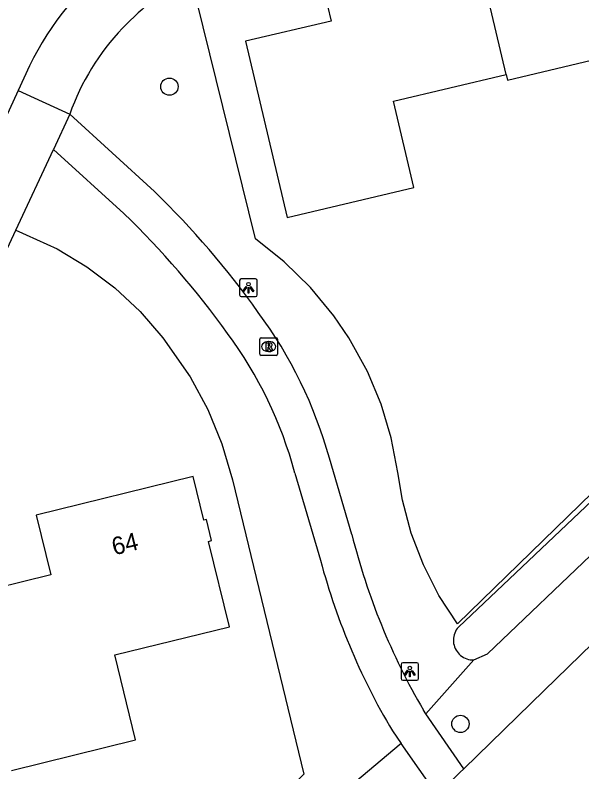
# Model space of a CAD drawing. Extents: x 157663 to 158496, y 379212 to 380934.
# Drawn here: x 158247.41 to 158279.59, y 380475.38 to 380518.31 of the extents above; entities that cross this region are included whole.
import ezdxf

# ---------------------------------------------------------------- set-up
doc = ezdxf.new("R2010")
doc.units = 0
for name, color, linetype in [('IMGEO_Berm_groen', 7, 'Continuous'), ('IMGEO_Boom', 7, 'Continuous'), ('IMGEO_Groenvoorziening', 7, 'Continuous'), ('IMGEO_Lichtpunt', 7, 'Continuous'), ('IMGEO_Pand', 7, 'Continuous'), ('IMGEO_Pand_nummerreeks', 7, 'Continuous'), ('IMGEO_Rijbaan_lokaal_gesloten', 7, 'Continuous'), ('IMGEO_Rijbaan_lokaal_open', 7, 'Continuous'), ('IMGEO_Rioolput', 7, 'Continuous'), ('IMGEO_Voetpad_open', 7, 'Continuous'), ('IMGEO_Waterloop', 7, 'Continuous')]:
    doc.layers.add(name, color=color, linetype=linetype)

msp = doc.modelspace()

# ---------------------------------------------------------------- linework, layer by layer
at = {"layer": 'IMGEO_Berm_groen'}
msp.add_lwpolyline([(158269.334, 380476.98), (158265.254, 380473.57)], dxfattribs=at)
at = {"layer": 'IMGEO_Boom'}
for centre in [(158256.174, 380514.25), (158272.696, 380478.099)]:
    msp.add_circle(centre, 0.489, dxfattribs=at)
at = {"layer": 'IMGEO_Groenvoorziening'}
for points in [[(158329.422, 380539.101), (158289.215, 380500), (158272.525, 380483.772), (158271.474, 380485.392), (158270.597, 380487.114), (158269.906, 380488.917), (158269.406, 380490.783), (158269.143, 380492.356), (158268.772, 380494.324), (158268.197, 380496.241), (158267.425, 380498.089), (158266.367, 380500), (158265.516, 380501.245), (158264.187, 380502.857), (158262.697, 380504.321), (158261.062, 380505.621), (158257.353, 380520.65)], [(158247.453, 380506.107), (158249.805, 380505.05), (158251.493, 380504.031), (158253.066, 380502.84), (158254.505, 380501.492), (158255.796, 380500), (158257.354, 380497.789), (158258.356, 380495.931), (158259.158, 380493.979), (158259.752, 380491.953), (158263.809, 380475.249), (158204.989, 380417.99)], [(158270.73, 380478.676), (158273.465, 380481.728)]]:
    msp.add_lwpolyline(points, dxfattribs=at)
at = {"layer": 'IMGEO_Lichtpunt'}
for p, q in [((158260.161, 380503.246), (158260.161, 380502.439)), ((158260.161, 380503.246), (158260.161, 380502.439)), ((158261.063, 380503.341), (158260.255, 380503.341)), ((158261.063, 380503.341), (158260.255, 380503.341)), ((158261.157, 380502.439), (158261.157, 380503.246)), ((158261.157, 380502.439), (158261.157, 380503.246)), ((158260.255, 380502.345), (158261.063, 380502.345)), ((158260.255, 380502.345), (158261.063, 380502.345)), ((158269.324, 380481.474), (158269.324, 380480.667)), ((158269.324, 380481.474), (158269.324, 380480.667)), ((158270.226, 380481.569), (158269.418, 380481.569)), ((158270.226, 380481.569), (158269.418, 380481.569)), ((158270.32, 380480.667), (158270.32, 380481.474)), ((158270.32, 380480.667), (158270.32, 380481.474)), ((158269.418, 380480.573), (158270.226, 380480.573)), ((158269.418, 380480.573), (158270.226, 380480.573))]:
    msp.add_line(p, q, dxfattribs=at)
for points in [[(158260.535, 380502.91), (158260.574, 380502.882), (158260.386, 380502.62), (158260.348, 380502.647), (158260.535, 380502.91)], [(158260.637, 380502.862), (158260.684, 380502.862), (158260.684, 380502.54), (158260.637, 380502.54), (158260.637, 380502.862)], [(158260.747, 380502.882), (158260.785, 380502.909), (158260.972, 380502.647), (158260.933, 380502.619), (158260.747, 380502.882)], [(158269.698, 380481.138), (158269.737, 380481.11), (158269.549, 380480.848), (158269.511, 380480.875), (158269.698, 380481.138)], [(158269.8, 380481.09), (158269.847, 380481.09), (158269.847, 380480.768), (158269.8, 380480.768), (158269.8, 380481.09)], [(158269.91, 380481.11), (158269.948, 380481.137), (158270.135, 380480.875), (158270.096, 380480.847), (158269.91, 380481.11)]]:
    msp.add_lwpolyline(points, dxfattribs=at)
for centre in [(158260.66, 380503.044), (158269.823, 380481.272)]:
    msp.add_circle(centre, 0.0994, dxfattribs=at)
for centre, start, end in [((158260.255, 380503.246), 90, 180), ((158260.255, 380503.246), 90, 180), ((158261.063, 380503.246), 0, 90), ((158261.063, 380503.246), 0, 90), ((158260.255, 380502.439), 180, 270), ((158260.255, 380502.439), 180, 270), ((158261.063, 380502.439), 270, 0), ((158261.063, 380502.439), 270, 360), ((158269.418, 380481.474), 90, 180), ((158269.418, 380481.474), 90, 180), ((158270.226, 380481.474), 0, 90), ((158270.226, 380481.474), 0, 90), ((158269.418, 380480.667), 180, 270), ((158269.418, 380480.667), 180, 270), ((158270.226, 380480.667), 270, 0), ((158270.226, 380480.667), 270, 360)]:
    msp.add_arc(centre, 0.0946, start, end, dxfattribs=at)
at = {"layer": 'IMGEO_Pand'}
for points in [[(158273.263, 380523.53), (158264.531, 380521.468), (158265.356, 380517.973), (158260.494, 380516.825), (158262.853, 380506.832), (158270.056, 380508.533), (158268.901, 380513.427), (158275.292, 380514.936)], [(158275.292, 380514.936), (158273.263, 380523.53)], [(158275.292, 380514.936), (158275.366, 380514.621), (158282.528, 380516.311), (158281.366, 380521.23), (158287.8, 380522.749)], [(158247.21, 380475.457), (158254.256, 380477.189), (158253.072, 380482.008), (158259.581, 380483.607), (158258.391, 380488.452), (158258.568, 380488.496), (158258.274, 380489.691), (158258.127, 380489.655), (158257.519, 380492.133), (158248.601, 380489.942), (158249.435, 380486.546), (158244.664, 380485.374), (158245.461, 380482.13)]]:
    msp.add_lwpolyline(points, dxfattribs=at)
at = {"layer": 'IMGEO_Rijbaan_lokaal_gesloten'}
for points in [[(158339.285, 380540.082), (158298.039, 380500), (158277.441, 380479.984), (158272.883, 380475.555)], [(158272.883, 380475.555), (158272.656, 380475.334), (158271.369, 380474.079)]]:
    msp.add_lwpolyline(points, dxfattribs=at)
at = {"layer": 'IMGEO_Rijbaan_lokaal_open'}
for points in [[(158248.235, 380515.431), (158247.594, 380514.038)], [(158247.594, 380514.038), (158242.804, 380503.631), (158240.314, 380498.123), (158239.292, 380495.89)]]:
    msp.add_lwpolyline(points, dxfattribs=at)
msp.add_arc((158263.673, 380507.946), 17.156, 127.2371, 154.1336, dxfattribs=at)
at = {"layer": 'IMGEO_Rioolput'}
for p, q in [((158261.31, 380499.079), (158261.31, 380499.931)), ((158261.385, 380500.005), (158262.237, 380500.005)), ((158261.798, 380499.785), (158261.823, 380499.785)), ((158262.311, 380499.931), (158262.311, 380499.079)), ((158262.237, 380499.005), (158261.385, 380499.005)), ((158261.821, 380499.225), (158261.796, 380499.225))]:
    msp.add_line(p, q, dxfattribs=at)
for points in [[(158261.31, 380499.079), (158261.31, 380499.931)], [(158261.385, 380500.005), (158262.237, 380500.005)], [(158262.311, 380499.931), (158262.311, 380499.079)], [(158261.899, 380499.703), (158261.647, 380499.705), (158261.647, 380499.305)], [(158261.647, 380499.305), (158261.771, 380499.305), (158261.771, 380499.467), (158261.782, 380499.467)], [(158261.825, 380499.624), (158261.771, 380499.624), (158261.771, 380499.543)], [(158261.771, 380499.543), (158261.823, 380499.543)], [(158261.829, 380499.438), (158261.9, 380499.305), (158262.04, 380499.305), (158261.975, 380499.431)], [(158262.237, 380499.005), (158261.385, 380499.005)]]:
    msp.add_lwpolyline(points, dxfattribs=at)
for centre, radius, start, end in [((158261.387, 380499.929), 0.0765, 91.552, 178.448), ((158261.387, 380499.929), 0.0765, 91.552, 178.448), ((158262.235, 380499.929), 0.0765, 1.552, 88.448), ((158262.235, 380499.929), 0.0765, 1.552, 88.448), ((158261.781, 380499.414), 0.0533, 26.0293, 88.6989), ((158261.807, 380499.732), 0.19, 274.7715, 282.9687), ((158261.831, 380499.528), 0.0964, 77.0061, 93.1865), ((158261.845, 380499.585), 0.0378, 276.6634, 79.6772), ((158261.898, 380499.593), 0.109, 350.3612, 89.416), ((158261.896, 380499.593), 0.112, 277.5842, 350.9817), ((158261.88, 380499.378), 0.108, 29.5134, 73.7905), ((158261.387, 380499.081), 0.0765, 181.552, 268.448), ((158261.387, 380499.081), 0.0765, 181.552, 268.448), ((158262.235, 380499.081), 0.0765, 271.552, 358.448), ((158262.235, 380499.081), 0.0765, 271.552, 358.448)]:
    msp.add_arc(centre, radius, start, end, dxfattribs=at)
for centre, major_axis, ratio, start_param, end_param in [((158261.797, 380499.505), (-0.387, 0.002), 0.722429, 4.712389, 7.853982), ((158261.822, 380499.505), (-0.39, 0.002), 0.717154, 1.570796, 4.712389)]:
    msp.add_ellipse(centre, major_axis=major_axis, ratio=ratio, start_param=start_param, end_param=end_param, dxfattribs=at)
at = {"layer": 'IMGEO_Voetpad_open'}
for points in [[(158247.594, 380514.038), (158250.517, 380512.693)], [(158250.517, 380512.693), (158249.589, 380510.681)], [(158255.325, 380508.305), (158250.517, 380512.693)], [(158247.453, 380506.107), (158249.589, 380510.681)], [(158249.589, 380510.681), (158253.591, 380507.049)], [(158241.856, 380493.971), (158245.11, 380501.089), (158247.453, 380506.107)], [(158266.53, 380488.852), (158265.256, 380493.17)], [(158263.298, 380492.332), (158264.661, 380487.712)], [(158270.73, 380478.676), (158270.591, 380478.878)], [(158272.883, 380475.555), (158270.73, 380478.676)], [(158268.832, 380477.696), (158269.334, 380476.98)], [(158271.369, 380474.079), (158269.334, 380476.98)]]:
    msp.add_lwpolyline(points, dxfattribs=at)
for centre, radius, start, end in [((158266.843, 380504.904), 18.385, 121.0776, 136.4924), ((158263.377, 380508.142), 13.641, 136.3346, 160.5134), ((158219.142, 380471.243), 51.796, 35.6688, 45.6876), ((158219.256, 380471.391), 49.501, 35.6629, 46.083), ((158240.763, 380486.348), 25.425, 15.5636, 36.4254), ((158240.611, 380486.26), 23.485, 14.9846, 36.5662), ((158303.644, 380498.15), 38.261, 194.064, 210.2442), ((158301.93, 380497.356), 38.496, 194.5074, 210.7096)]:
    msp.add_arc(centre, radius, start, end, dxfattribs=at)
at = {"layer": 'IMGEO_Waterloop'}
for points in [[(158273.465, 380481.728), (158274.224, 380482.069), (158293.02, 380500), (158332.358, 380537.527), (158332.462, 380538.012)], [(158289.923, 380500), (158272.577, 380483.594), (158272.514, 380483.516), (158272.458, 380483.433), (158272.41, 380483.344), (158272.37, 380483.252), (158272.338, 380483.157), (158272.315, 380483.06), (158272.3, 380482.96), (158272.295, 380482.86), (158272.299, 380482.76), (158272.311, 380482.66), (158272.332, 380482.562), (158272.363, 380482.466), (158272.401, 380482.373), (158272.448, 380482.284), (158272.502, 380482.2), (158272.564, 380482.121), (158272.632, 380482.047), (158272.707, 380481.98), (158272.788, 380481.92), (158272.873, 380481.868), (158272.963, 380481.823), (158273.056, 380481.787), (158273.153, 380481.759), (158273.251, 380481.739), (158273.351, 380481.729), (158273.452, 380481.728), (158273.465, 380481.728)]]:
    msp.add_lwpolyline(points, dxfattribs=at)

# ---------------------------------------------------------------- texts
at = {"layer": 'IMGEO_Pand_nummerreeks'}
msp.add_text('64', height=1, rotation=13.8026, dxfattribs=at).set_placement((158253.04, 380487.655))

doc.saveas('drawing.dxf')
